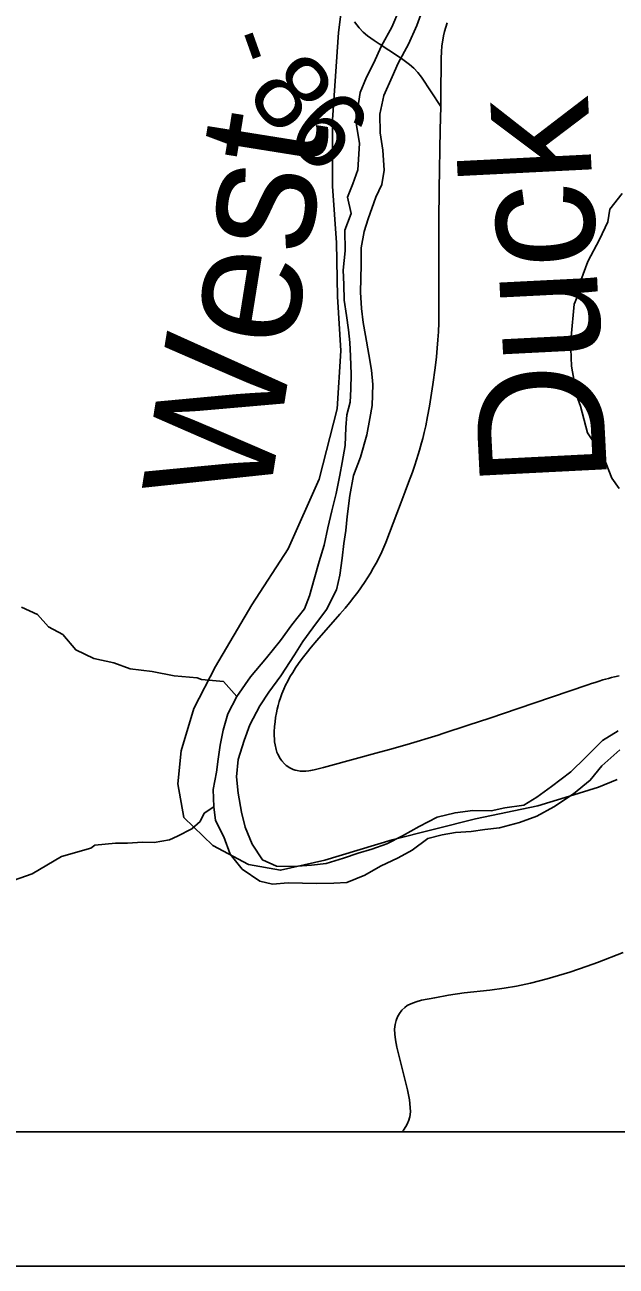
# Model space of a CAD drawing. Extents: x 0 to 34, y -8.9 to 22.
# Drawn here: x 24.135 to 24.574, y 14.5 to 15.423 of the extents above; entities that cross this region are included whole.
import ezdxf

# ---------------------------------------------------------------- set-up
doc = ezdxf.new("R2010")
doc.units = 0
for name, color, linetype in [('GM_X_Corporation', 7, 'Continuous'), ('GM_X_Major_River', 7, 'Continuous'), ('GM_X_Major_River_Text', 7, 'Continuous'), ('GM_X_Minor_River', 7, 'Continuous'), ('GM_X_Rail_Line', 7, 'Continuous'), ('GM_X_State_Route', 7, 'Continuous'), ('GM_X_Township_Road', 7, 'Continuous'), ('GM_X_Township_Road_Text', 7, 'Continuous'), ('SH_Data', 7, 'Continuous')]:
    doc.layers.add(name, color=color, linetype=linetype)

msp = doc.modelspace()

# ---------------------------------------------------------------- linework, layer by layer
at = {"layer": 'GM_X_Corporation'}
msp.add_lwpolyline([(23.71667, 19.34001), (23.71667, 14.6), (30.51667, 14.6)], dxfattribs=at)
msp.add_lwpolyline([(23.71667, 15.99131), (23.71667, 14.6), (28.17389, 14.6), (28.1809, 15.29867), (28.19184, 16.15092), (28.18456, 16.33414), (28.1817, 16.6637), (28.19281, 16.80535), (28.18821, 17.31083), (27.91098, 17.31044), (27.47976, 17.3159), (27.05609, 17.31174), (26.72923, 17.31694), (26.39404, 17.3229), (26.13606, 17.32776), (26.13505, 17.30548), (26.11864, 15.93664), (25.79223, 15.93902), (25.67852, 15.94183), (24.82679, 15.96404), (24.27706, 15.98069), (24.06511, 15.98282)], close=True, dxfattribs=at)
at = {"layer": 'GM_X_Major_River'}
for points in [[(24.41303, 15.43504), (24.40752, 15.42169), (24.39975, 15.40793), (24.39386, 15.39457), (24.38869, 15.38464), (24.38392, 15.37319), (24.38182, 15.35989), (24.38121, 15.34888), (24.38329, 15.33525), (24.38204, 15.31551), (24.37839, 15.30521), (24.37435, 15.2953), (24.37717, 15.28319), (24.37241, 15.27061), (24.37262, 15.25544), (24.3713, 15.241), (24.37182, 15.23039), (24.37198, 15.21863), (24.37365, 15.20727), (24.37531, 15.19667), (24.37619, 15.1872), (24.37671, 15.17696), (24.37727, 15.16369), (24.37705, 15.15231), (24.37641, 15.14282), (24.37389, 15.1333), (24.37326, 15.12381), (24.37268, 15.11052), (24.37058, 15.09797), (24.36881, 15.08846), (24.36596, 15.07477), (24.36272, 15.06182), (24.35986, 15.04927), (24.357, 15.03633), (24.35338, 15.02414), (24.34976, 15.01119), (24.34614, 14.99862), (24.34248, 14.98909), (24.33316, 14.9772), (24.3246, 14.96533), (24.31415, 14.95266), (24.30221, 14.93846), (24.29217, 14.92391), (24.28553, 14.91092), (24.2819, 14.89873), (24.27977, 14.8877), (24.2784, 14.87706), (24.27701, 14.86756), (24.27453, 14.85463), (24.27509, 14.84173), (24.27636, 14.83151), (24.28259, 14.81945), (24.28732, 14.80662), (24.29619, 14.79535), (24.3092, 14.78642), (24.3187, 14.78428), (24.33044, 14.78519), (24.35168, 14.78472), (24.36419, 14.78489), (24.37404, 14.78541), (24.38724, 14.79089), (24.3989, 14.7975), (24.41208, 14.80375), (24.42262, 14.80958), (24.43426, 14.81809), (24.44484, 14.82088), (24.45467, 14.82254), (24.46641, 14.82345), (24.47663, 14.82473), (24.48761, 14.82602), (24.50234, 14.83001), (24.51517, 14.83474), (24.52796, 14.84174), (24.54262, 14.85142), (24.55499, 14.86145), (24.56357, 14.87219), (24.57705, 14.88414)], [(24.57573, 14.89816), (24.56407, 14.89117), (24.55135, 14.87848), (24.5405, 14.86771), (24.52624, 14.85689), (24.51535, 14.84878), (24.50558, 14.84295), (24.49158, 14.84087), (24.48137, 14.83883), (24.46772, 14.83903), (24.45447, 14.83733), (24.44125, 14.83412), (24.42769, 14.8271), (24.41527, 14.82011), (24.4036, 14.81426), (24.39266, 14.81032), (24.38247, 14.80714), (24.37152, 14.80358), (24.35868, 14.79961), (24.34771, 14.79833), (24.33407, 14.79738), (24.32156, 14.79759), (24.31125, 14.80239), (24.30352, 14.81404), (24.29842, 14.82649), (24.29561, 14.83784), (24.29315, 14.85184), (24.29185, 14.86397), (24.29319, 14.87688), (24.29755, 14.89098), (24.30194, 14.9028), (24.30933, 14.91694), (24.31602, 14.92689), (24.32495, 14.93915), (24.33498, 14.95484), (24.34129, 14.96479), (24.34874, 14.97476), (24.35878, 14.98855), (24.36617, 15.00307), (24.36868, 15.0141), (24.3704, 15.02664), (24.37177, 15.03767), (24.37316, 15.04717), (24.37415, 15.05781), (24.37622, 15.07339), (24.37905, 15.08822), (24.38417, 15.10195), (24.38888, 15.11833), (24.39099, 15.13049), (24.39275, 15.14038), (24.3933, 15.15594), (24.3924, 15.16656), (24.39034, 15.17829), (24.38788, 15.19229), (24.38623, 15.20213), (24.38495, 15.21236), (24.38403, 15.22449), (24.38451, 15.24498), (24.38472, 15.2575), (24.38683, 15.26966), (24.38974, 15.27919), (24.39558, 15.2952), (24.40001, 15.30475), (24.40176, 15.31539), (24.4008, 15.33017), (24.39873, 15.34304), (24.39854, 15.35708), (24.40139, 15.37077), (24.40764, 15.38489), (24.41206, 15.39482), (24.41983, 15.40896), (24.42608, 15.42308), (24.43011, 15.43376)]]:
    msp.add_lwpolyline(points, dxfattribs=at)
at = {"layer": 'GM_X_Minor_River'}
for points in [[(24.57653, 15.07858), (24.57108, 15.08609), (24.56474, 15.10196), (24.56044, 15.10873), (24.55304, 15.12002), (24.54776, 15.13969), (24.54497, 15.14725), (24.54117, 15.16961), (24.54057, 15.18252), (24.5408, 15.19127), (24.54304, 15.21563), (24.54778, 15.22672), (24.54805, 15.23319), (24.55312, 15.24733), (24.56195, 15.26381), (24.56818, 15.27683), (24.56953, 15.28635), (24.57882, 15.2979)], [(24.29217, 14.92391), (24.28214, 14.93484), (24.26579, 14.93649), (24.26273, 14.93758), (24.24562, 14.93921), (24.22924, 14.94237), (24.21288, 14.94439), (24.20066, 14.94876), (24.1858, 14.95195), (24.1724, 14.95858), (24.16272, 14.96983), (24.15199, 14.97574), (24.14386, 14.98473), (24.132, 14.99025)], [(24.27509, 14.84173), (24.26788, 14.83695), (24.26495, 14.83082), (24.25859, 14.8254), (24.24805, 14.81991), (24.24203, 14.81716), (24.23067, 14.81508), (24.22194, 14.81532), (24.21094, 14.81477), (24.20183, 14.81463), (24.18667, 14.81325), (24.18367, 14.81092), (24.16176, 14.80487), (24.13997, 14.79199), (24.11657, 14.78364)]]:
    msp.add_lwpolyline(points, dxfattribs=at)
at = {"layer": 'GM_X_Rail_Line'}
msp.add_lwpolyline([(24.37743, 15.49467), (24.36784, 15.41786), (24.36341, 15.35286), (24.3634, 15.30338), (24.36635, 15.26128), (24.36709, 15.22139), (24.36949, 15.18093), (24.36677, 15.13767), (24.35328, 15.08535), (24.33033, 15.03352), (24.30328, 14.99201), (24.27618, 14.94599), (24.2602, 14.9148), (24.25081, 14.8833), (24.24823, 14.85891), (24.25267, 14.83385), (24.27441, 14.81303), (24.30095, 14.79875), (24.32466, 14.79448), (24.35767, 14.80203), (24.40772, 14.81708), (24.46962, 14.83266), (24.51598, 14.84249), (24.5396, 14.8497), (24.56121, 14.85634), (24.57511, 14.86196)], dxfattribs=at)
at = {"layer": 'GM_X_State_Route'}
for points in [[(24.41872, 14.88815), (24.40572, 14.88439), (24.3956, 14.88157), (24.36209, 14.87236), (24.35671, 14.87096), (24.34956, 14.86918), (24.3482, 14.8689), (24.34697, 14.86869), (24.3457, 14.86852), (24.34352, 14.86832), (24.3414, 14.86823), (24.33933, 14.86836), (24.3371, 14.86865), (24.33554, 14.86906), (24.3341, 14.86953), (24.33308, 14.86992), (24.33197, 14.87049), (24.33102, 14.87103), (24.33001, 14.87176), (24.32891, 14.87256), (24.32771, 14.87365), (24.3257, 14.87584), (24.32488, 14.87699), (24.324, 14.87829), (24.32332, 14.87954), (24.32264, 14.88095), (24.322, 14.8825), (24.32142, 14.88434), (24.32061, 14.88788), (24.32028, 14.88997), (24.32007, 14.89203), (24.31995, 14.89467), (24.32003, 14.8976), (24.32023, 14.9014), (24.32059, 14.90496), (24.32097, 14.90827), (24.32155, 14.91164), (24.32217, 14.91439), (24.32285, 14.91704), (24.32373, 14.91999), (24.32463, 14.92292), (24.32566, 14.92573), (24.32709, 14.92921), (24.32841, 14.93215), (24.33001, 14.93532), (24.33162, 14.93835), (24.33369, 14.94172), (24.33589, 14.94506), (24.33815, 14.94838), (24.34074, 14.95204), (24.34373, 14.95578), (24.34741, 14.96043), (24.35159, 14.96535), (24.36873, 14.98501), (24.37263, 14.98954), (24.37595, 14.99358), (24.37928, 14.99769), (24.38205, 15.00147), (24.3871, 15.00861), (24.38932, 15.01198), (24.39145, 15.01547), (24.39364, 15.01923), (24.39575, 15.02309), (24.39796, 15.02729), (24.39995, 15.03147), (24.40152, 15.03498), (24.40289, 15.03836), (24.4111, 15.05986), (24.41445, 15.06847), (24.41734, 15.07617), (24.41993, 15.08305), (24.4228, 15.09078), (24.42445, 15.09577), (24.42582, 15.09992), (24.42712, 15.10377), (24.42807, 15.10701), (24.42886, 15.10971), (24.4296, 15.11251), (24.43043, 15.11562), (24.43156, 15.12028), (24.43265, 15.12524), (24.43404, 15.13204), (24.43544, 15.1398), (24.43651, 15.14612), (24.43799, 15.15591), (24.43972, 15.16831), (24.44062, 15.17652), (24.44126, 15.18294), (24.44174, 15.18904), (24.44211, 15.19514), (24.44238, 15.20188), (24.44236, 15.2082), (24.44232, 15.21365), (24.44228, 15.22422), (24.44236, 15.23986), (24.44241, 15.25032), (24.44247, 15.27758), (24.44252, 15.30127), (24.44346, 15.34543), (24.44383, 15.36259), (24.44399, 15.37498), (24.44403, 15.39358), (24.44411, 15.39876), (24.44436, 15.40336), (24.44469, 15.4078), (24.4453, 15.41198), (24.44584, 15.41528), (24.44664, 15.41859), (24.44756, 15.42177), (24.44865, 15.425)], [(24.57648, 14.9391), (24.57307, 14.93836), (24.57077, 14.93781), (24.56858, 14.93721), (24.56645, 14.93661), (24.56445, 14.93607), (24.56169, 14.93524), (24.55868, 14.93432), (24.55584, 14.93344), (24.55317, 14.93251), (24.52609, 14.92332), (24.50137, 14.91497), (24.4802, 14.90775), (24.46433, 14.90236), (24.44544, 14.89622), (24.44189, 14.89509), (24.41872, 14.88815)], [(24.41499, 14.6), (24.41617, 14.60125), (24.41783, 14.60398), (24.4189, 14.60558), (24.41996, 14.60858), (24.42066, 14.61045), (24.42078, 14.61108), (24.42122, 14.61489), (24.42119, 14.61805), (24.42058, 14.6237), (24.41915, 14.63107), (24.41548, 14.64614), (24.41125, 14.66296), (24.41012, 14.66837), (24.4096, 14.67259), (24.40951, 14.67619), (24.40986, 14.67976), (24.41054, 14.68265), (24.41163, 14.68541), (24.41306, 14.68801), (24.41488, 14.69034), (24.41704, 14.69238), (24.41892, 14.69381), (24.42155, 14.69519), (24.42549, 14.69676), (24.42959, 14.69788), (24.43933, 14.69972), (24.44968, 14.70164), (24.46131, 14.70325), (24.4804, 14.7054), (24.49089, 14.70675), (24.50011, 14.70831), (24.51045, 14.71057), (24.52308, 14.71387), (24.53974, 14.7188), (24.5527, 14.72317), (24.56027, 14.72596), (24.57936, 14.73327)]]:
    msp.add_lwpolyline(points, dxfattribs=at)
at = {"layer": 'GM_X_Township_Road'}
for points in [[(24.40871, 15.40226), (24.40526, 15.40456), (24.39802, 15.40936), (24.39439, 15.4117), (24.3893, 15.41522), (24.386, 15.41805), (24.38304, 15.42121), (24.37964, 15.42566)], [(24.44383, 15.36259), (24.42946, 15.38456), (24.42685, 15.38801), (24.42392, 15.39121), (24.42064, 15.39405), (24.4156, 15.39767), (24.40871, 15.40226)]]:
    msp.add_lwpolyline(points, dxfattribs=at)
at = {"layer": 'SH_Data'}
for points in [[(23.61667, 21.5), (30.61667, 21.5), (30.61667, 14.5), (23.61667, 14.5)], [(23.71667, 21.4), (30.51667, 21.4), (30.51667, 14.6), (23.71667, 14.6)]]:
    msp.add_lwpolyline(points, close=True, dxfattribs=at)

# ---------------------------------------------------------------- texts
at = {"layer": 'GM_X_Major_River_Text'}
for s, height, rotation, p in [('Duck', 0.094716, 92.89755, (24.56784, 15.08247)), ('West', 0.094717, 80.90042, (24.31498, 15.06343))]:
    msp.add_text(s, height=height, rotation=rotation, dxfattribs=at).set_placement(p)
at = {"layer": 'GM_X_Township_Road_Text'}
for s, rotation, p in [('-', 289.65195, (24.27909, 15.41241)), ('8', 310.0312, (24.29785, 15.37143)), ('6', 317.42191, (24.32588, 15.33885))]:
    msp.add_text(s, height=0.05682, rotation=rotation, dxfattribs=at).set_placement(p)

doc.saveas('drawing.dxf')
